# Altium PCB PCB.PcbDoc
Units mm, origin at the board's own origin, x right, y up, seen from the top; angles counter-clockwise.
Board outline 65.94 x 50 mm, 2 copper layers (Top Layer, Bottom Layer); 36 components, 28 nets, 111 pads, 85 vias.
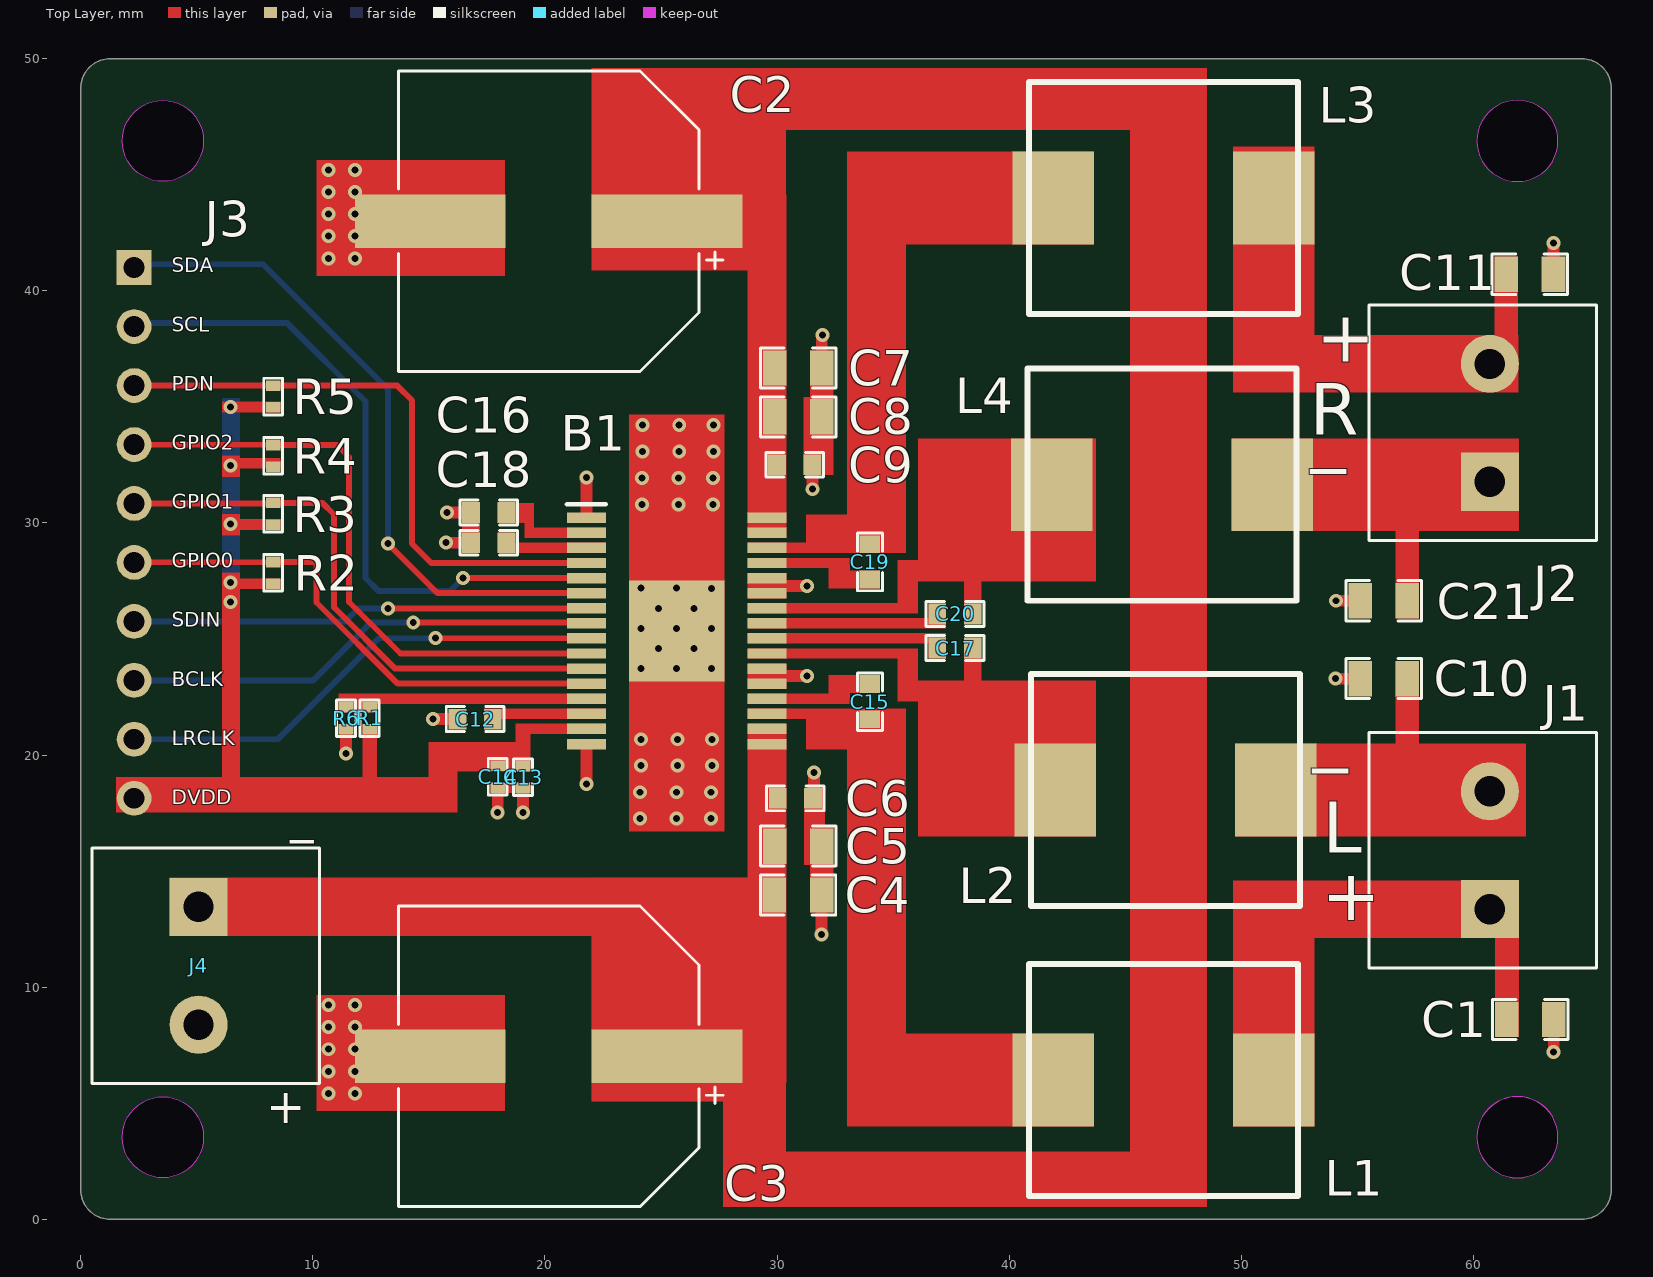
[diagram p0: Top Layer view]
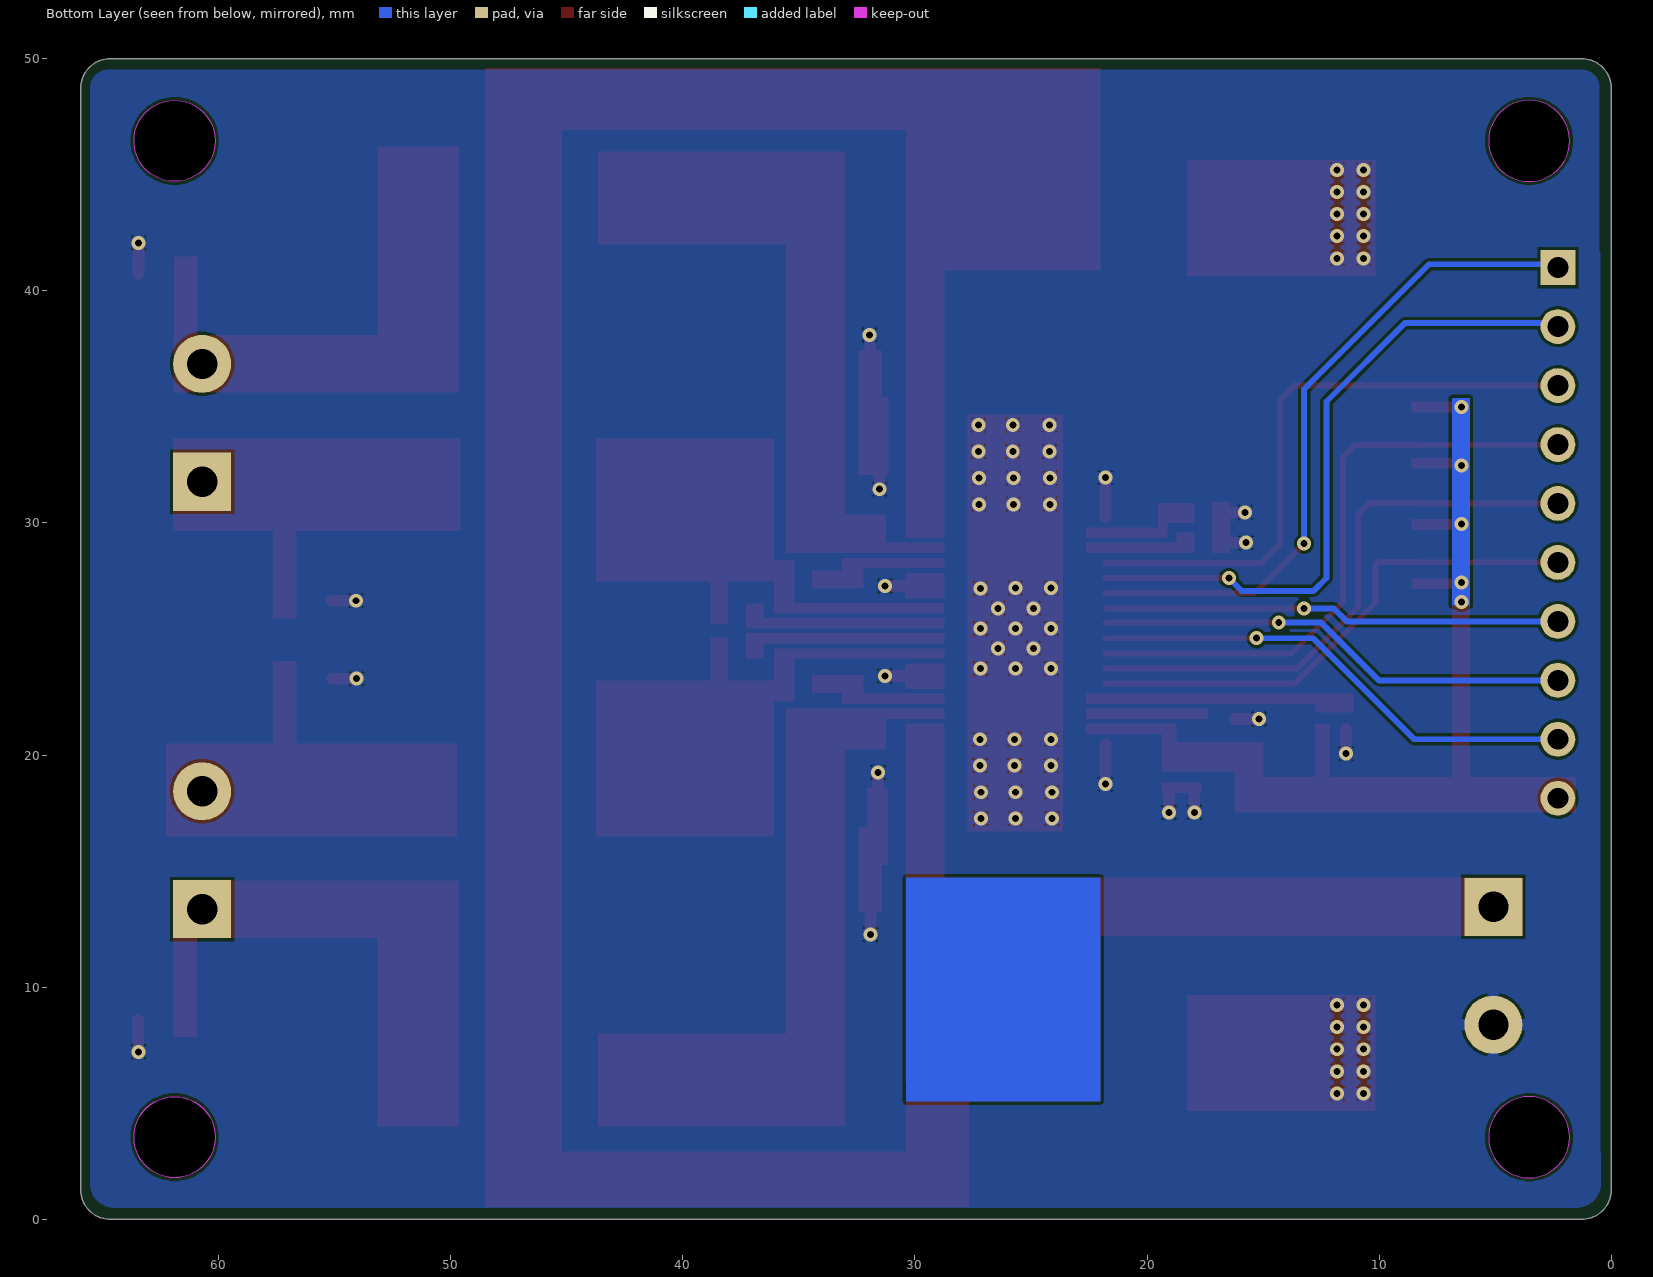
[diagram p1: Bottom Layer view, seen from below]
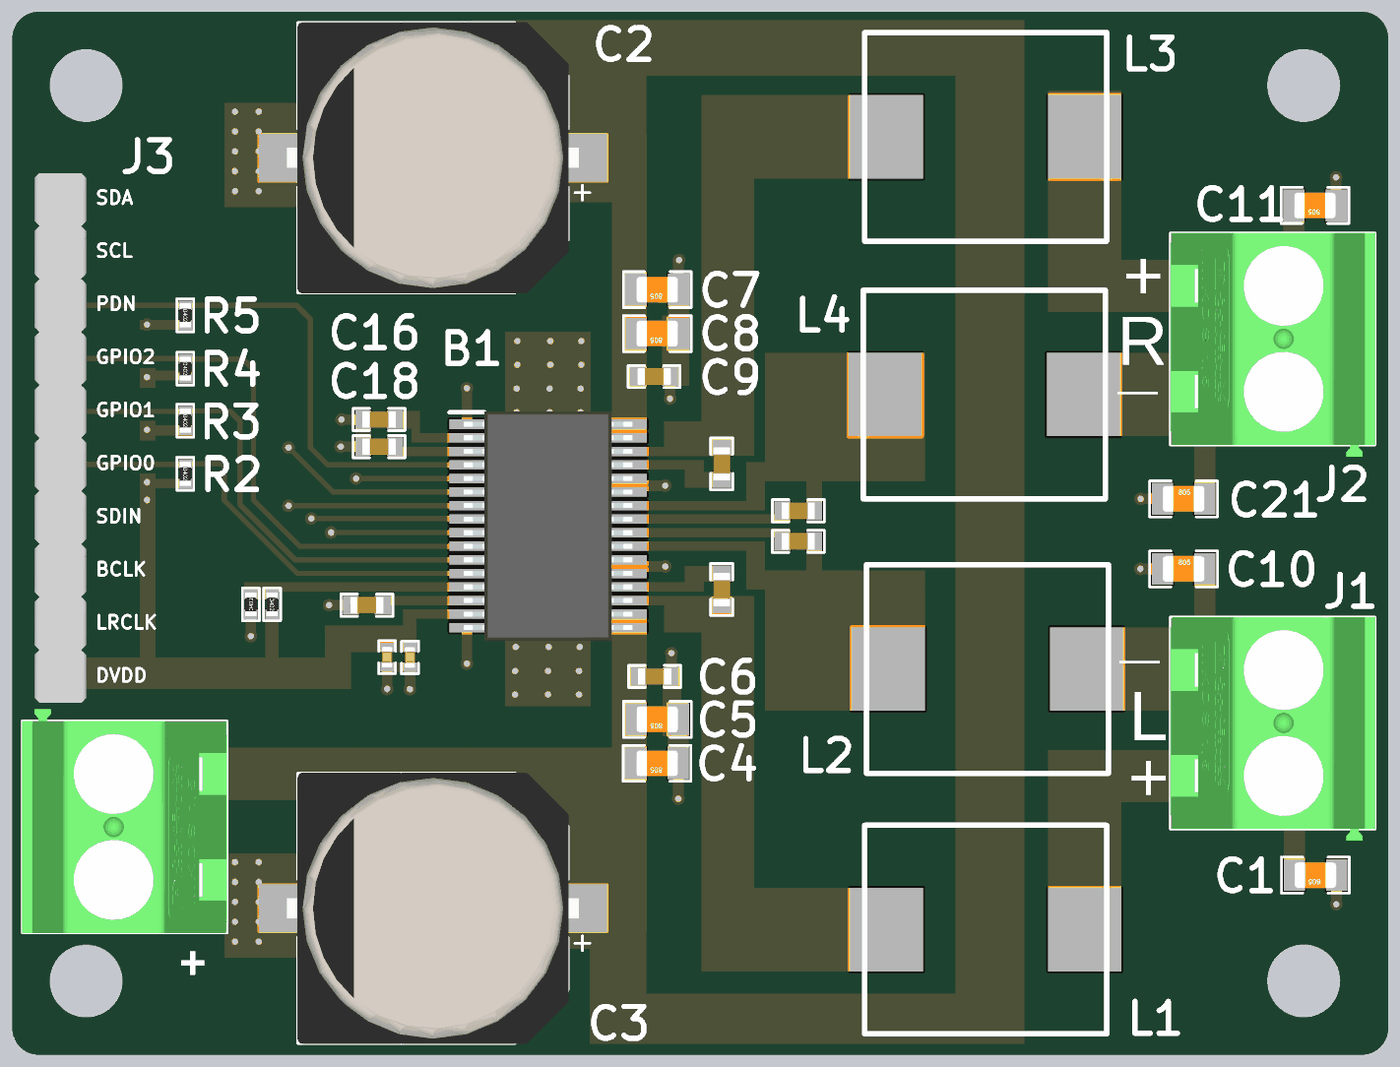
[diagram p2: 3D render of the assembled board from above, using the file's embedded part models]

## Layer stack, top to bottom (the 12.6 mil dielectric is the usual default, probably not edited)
Top Solder: solder mask 0.0102, Solder Resist, Dk 3.5
Top Layer: signal copper 0.0356
Dielectric 1: dielectric 0.32, FR-4, Dk 4.8
Bottom Layer: signal copper 0.0356
Bottom Solder: solder mask 0.0102, Solder Resist, Dk 3.5

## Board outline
1.27,0 cw(c1.27,1.27) 0,1.27 0,48.73 cw(c1.27,48.73) 1.27,50 64.668,50 cw(c64.668,48.73) 65.938,48.73 65.938,1.27 cw(c64.668,1.27) 64.668,0
cut-out: 60.142,3.54 ccw(c61.892,3.54) 61.892,1.79 ccw(c61.892,3.54) 63.642,3.54 ccw(c61.892,3.54) 61.892,5.29 ccw(c61.892,3.54)
cut-out: 60.142,3.536 ccw(c61.892,3.536) 61.892,1.786 ccw(c61.892,3.536) 63.642,3.536 ccw(c61.892,3.536) 61.892,5.286 ccw(c61.892,3.536)
cut-out: 60.142,46.464 ccw(c61.892,46.464) 61.892,44.714 ccw(c61.892,46.464) 63.642,46.464 ccw(c61.892,46.464) 61.892,48.214 ccw(c61.892,46.464)
cut-out: 3.536,44.714 cw(c3.536,46.464) 1.786,46.464 cw(c3.536,46.464) 3.536,48.214 cw(c3.536,46.464) 5.286,46.464 cw(c3.536,46.464)
cut-out: 3.536,1.786 cw(c3.536,3.536) 1.786,3.536 cw(c3.536,3.536) 3.536,5.286 cw(c3.536,3.536) 5.286,3.536 cw(c3.536,3.536)

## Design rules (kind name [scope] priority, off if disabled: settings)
Clearance [All] p1: gap=0.127 ignorepadtopadclearanceinfootprint=FALSE
HoleToHoleClearance [All] p1: gap=0.127 allowstackedmicrovias=TRUE
MinimumSolderMaskSliver [All] p1: minsoldermaskwidth=0
PolygonConnect [All] p1: connectstyle=Relief reliefconductorwidth=0.508 reliefentries=4 polygonreliefangle="90 Angle" airgapwidth=0.127
RoutingVias [All] p1: holewidth=0.3 width=0.6 viastyle="Through Hole" minholewidth=0.3 minwidth=0.6 maxholewidth=0.3 maxwidth=0.6
SilkToSilkClearance [All] p1: silktosilkclearance=0
SilkToSolderMaskClearance [IsPad] p1: minsilkscreentomaskgap=0 clearancetoexposedcopper=TRUE
SolderMaskExpansion [All] p1: expansion=0.102 istentingtop=FALSE
UnRoutedNet [All] p1: checkbadconnections=TRUE
Width [All] p1: maxlimit=1.27 minlimit=0.025 preferedwidth=0.254
25 further rules are at their usual default settings.

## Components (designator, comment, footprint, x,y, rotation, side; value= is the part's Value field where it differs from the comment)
B1 "TAS5828MDADR" SOP65P810X115-33M 25.673,25.351 r0 top
C1 "680nF" Cap-0805 62.454,8.611 r180 top
C2 "470uF" RVT470UF50V34RV0133 20.158,43 r180 top
C3 "470uF" RVT470UF50V34RV0133 20.158,7.021 r180 top
C4 "10uF" Cap-0805 30.902,13.97 r180 top
C5 "10uF" Cap-0805 30.912,16.078 r180 top
C6 "100nF" Cap-0603 30.785,18.136 r180 top
C7 "10uF" Cap-0805 30.907,36.678 r180 top
C8 "10uF" Cap-0805 30.907,34.569 r180 top
C9 "100nF" Cap-0603 30.759,32.512 r180 top
C10 "680nF" Cap-0805 56.134,23.292 r0 top
C11 "680nF" Cap-0805 62.433,40.716 r180 top
C12 "1uF" Cap-0603 16.992,21.551 r0 top
C13 "0.1uF" Cap-0402 19.054,19.05 r90 top value=100nF
C14 "0.1uF" Cap-0402 17.962,19.062 r90 top value=100nF
C15 "0.47uF" Cap-0603 34,22.3 r270 top
C16 "1uF" Cap-0603 17.577,30.451 r0 top
C17 "0.47uF" Cap-0603 37.668,24.613 r0 top
C18 "1uF" Cap-0603 17.577,29.151 r0 top
C19 "0.47uF" Cap-0603 34,28.325 r90 top
C20 "0.47uF" Cap-0603 37.668,26.079 r0 top
C21 "680nF" Cap-0805 56.134,26.648 r0 top
J1 "1715721" 1715721 60.706,15.9 r90 top
J2 "1715721" 1715721 60.706,34.315 r90 top
J3 "PZ254-1-10-Z-8.5" PZ254-1-10-Z-8.5 2.3,41 r270 top
J4 "1715721" 1715721 5.08,10.922 r270 top
L1 "10uH" BMRF00101040100MA1 41.899,6 r0 top
L2 "10uH" BMRF00101040100MA1 41.986,18.491 r0 top
L3 "10uH" BMRF00101040100MA1 41.899,44 r0 top
L4 "10uH" BMRF00101040100MA1 41.833,31.648 r0 top
R1 "0R" Res-0402 12.446,21.59 r270 top
R2 "10K" Res-0402 8.29,27.85 r270 top
R3 "10K" Res-0402 8.29,30.395 r270 top
R4 "10K" Res-0402 8.29,32.89 r270 top
R5 "10K" Res-0402 8.29,35.448 r270 top
R6 "0R" Res-0402 11.43,21.59 r90 top

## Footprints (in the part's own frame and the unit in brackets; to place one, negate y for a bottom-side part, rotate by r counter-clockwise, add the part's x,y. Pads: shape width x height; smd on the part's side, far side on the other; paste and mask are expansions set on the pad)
1715721 [mm]
  rect 2.5x2.5 / inner round 2.5 / far side rect 2.5x2.5 hole 1.3: 1(-2.54,0)
  round 2.5 hole 1.3: 2(2.54,0)
  silkscreen extent -5.08,-4.6 5.08,5.2, body extent -5.64,-4.62 5.09,5.21, height 14.2
BMRF00101040100MA1 [mm]
  rect 3.5x4 smd: 1(0,0) 2(9.5,0)
  silkscreen extent -1.05,-5 10.55,5, body extent -1.02,-4.95 10.54,4.95, height 4
Cap-0402 [mil]
  rect 18x25 smd mask+2.36: 1(-18.5,0) 2(18.5,0)
  silkscreen extent -31,-16 31,16, body extent -20,-10 20,10, height 19
Cap-0603 [mil]
  rect 30x35 smd mask+2.36: 1(-30,0) 2(30,0)
  silkscreen extent -49,-21 49,21, body extent -32,-16 31,16, height 34
Cap-0805 [mil] "SMD 0805"
  rect 40x60 smd mask+2.76: 1(-40,0) 2(40,0)
  silkscreen extent -64,-34 64,34, body extent -39,-25 39,25, height 30
PZ254-1-10-Z-8.5 [mm]
  rect 1.5x1.5 hole 0.9: 1(0,0)
  round 1.5 hole 0.9: 2(2.54,0) 3(5.08,0) 4(7.62,0) 5(10.16,0) 6(12.7,0) 7(15.24,0) 8(17.78,0) 9(20.32,0) 10(22.86,0)
  body extent -1.27,-1.25 24.13,1.25, height 9.51
Res-0402 [mil]
  rect 18x25 smd mask+2.17: 1(-18.5,0) 2(18.5,0)
  silkscreen extent -32,-17 32,16, body extent -23,-11 23,11, height 16
RVT470UF50V34RV0133 [mm]
  rect 6.5x2.3 smd paste+0 mask+0.051: 1(-5.1,0) 2(5.1,0)
  silkscreen extent -7.52,-6.48 6.48,6.48, body extent -7,-6.5 7,6.5, height 13.5
SOP65P810X115-33M [mm]
  rect 1.675x0.45 smd: 1(-3.888,4.875) 2(-3.888,4.225) 3(-3.888,3.575) 4(-3.888,2.925) 5(-3.888,2.275) 6(-3.888,1.625) 7(-3.888,0.975) 8(-3.888,0.325) 9(-3.888,-0.325) 10(-3.888,-0.975) 11(-3.888,-1.625) 12(-3.888,-2.275) 13(-3.888,-2.925) 14(-3.888,-3.575) 15(-3.888,-4.225) 16(-3.888,-4.875) 17(3.888,-4.875) 18(3.888,-4.225) 19(3.888,-3.575) 20(3.888,-2.925) 21(3.888,-2.275) 22(3.888,-1.625) 23(3.888,-0.975) 24(3.888,-0.325) 25(3.888,0.325) 26(3.888,0.975) 27(3.888,1.625) 28(3.888,2.275) 29(3.888,2.925) 30(3.888,3.575) 31(3.888,4.225) 32(3.888,4.875)
  rect 4.11x4.36 smd: 33(0,0)
  silkscreen extent -4.72,5.45 -3.05,5.45, body extent -4.05,-5.5 4.05,5.5, height 1.15

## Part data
B1: "Audio Amplifiers 50-W stereo, digital input, high-performance, closed-loop, Class-D, with integrated audio processor 32-HTSSOP -40 to 85", LCSC Part Number=C5214953, Manufacturer_Name="Texas Instruments", Mouser Part Number=595-TAS5828MDADR
C1 C10 C11 C21: library part CC0805KKX7R9BB684, "50V 680nF X7R ±10% 0805 Multilayer Ceramic Capacitors MLCC - SMD/SMT ROHS", LCSC Part Number=C107133, Manufacturer=YAGEO, Package=0805
C2 C3: library part RVT470UF50V34RV0133, "470uF 50V 50mA@120Hz ±20% SMD,D12.5xL13.5mm Aluminum Electrolytic Capacitors - SMD ROHS", LCSC Part Number=C2837182, Manufacturer=KNSCHA
C4 C5 C7 C8: library part CC0805KKX5R8BB106, "CAP CER 10UF 25V X5R 0805", Case Code (Imperial)=0805, Case Code (Metric)=2012, Dielectric=X5R, LCSC Part Number=C89831, Manufacturer=Yageo, Max Operating Temperature=85°C, Min Operating Temperature=-55°C, Resistor Type=Ceramic, Supplier Part Number 1=311-1869-1-ND, Tolerance=10%, Voltage Rating=25V
C6 C9: library part CC0603KRX5R9BB104, "CAP CER 0.1UF 50V X5R 0603", Case Code (Imperial)=0603, Case Code (Metric)=1608, Dielectric=X5R, LCSC Part Number=C110022, Manufacturer=Yageo, Max Operating Temperature=85°C, Min Operating Temperature=-55°C, Package Quantity=4000, Supplier Part Number 1=311-4046-1-ND, Tolerance=10%, Voltage Rating=50V
C12 C16 C18: library part CC0603KRX5R8BB105, "CAP CER 1UF 25V X5R 0603", Case Code (Imperial)=0603, Case Code (Metric)=1608, Dielectric=X5R, LCSC Part Number=C14664, Manufacturer=Yageo, Max Operating Temperature=85°C, Min Operating Temperature=-55°C, Package Quantity=1, Supplier Part Number 1=311-1445-1-ND, Tolerance=10%, Voltage Rating=25V
C13 C14: library part CC0402JRX7R7BB104, "CAP CER 0.1UF 16V X7R 0402", Case Code (Imperial)=0402, Case Code (Metric)=1005, Dielectric=X7R, LCSC Part Number=C541464, Manufacturer=Yageo, Max Operating Temperature=125°C, Min Operating Temperature=-55°C, Package Quantity=10000, Supplier Part Number=311-1676-1-ND, Tolerance=5%, Voltage Rating=16V
C15 C17 C19 C20: library part CC0603KRX5R9BB474, "CAP CER 0.47UF 50V X5R 0603", Capacitance=470nF, Case/Package=0603, Dielectric=X5R, LCSC Part Number=C513651, Manufacturer=Yageo, Max Operating Temperature=85°C, Min Operating Temperature=-55°C, Supplier Part Number 1=311-4047-1-ND, Tolerance=10%, Voltage Rating=50V
J1 J2 J4: "TERM BLK 2P SIDE ENT 5.08MM PCB", LCSC Part Number=C480516, Manufacturer="Phoenix Contact", Supplier Part Number=277-1263-ND
J3: "3A Direct Insert Policy 2.5mm 260℃@10S 10P 6mm -40℃~+105℃ 3mm 2.54mm Single Row Black Brass 1x10P Plugin,P=2.54mm Pin Headers ROHS", LCSC Part Number=C2894933, Manufacturer=HCTL, Package=Plugin,P{}2.54mmPlugin,P{}2.54mm
L1 L2 L3 L4: library part BMRF00101040100MA1, "6.5A 10uH Shielded inductor ±20% 7A Power Inductors ROHS", LCSC Part Number=C2903677, Manufacturer="Chilisin Elec", Package=-
R1 R6: library part RC0402FR-070RL, "RES 0 OHM JUMPER 1/16W 0402", Case Code (Imperial)=0402, Case Code (Metric)=1005, LCSC Part Number=C106231, Manufacturer=Yageo, Max Operating Temperature=155°C, Max Power Dissipation=63mW, Min Operating Temperature=-55°C, Power Rating=62.5mW, Resistor Type="Thick Film", Supplier Part Number 1=603-RC0402FR-070RL, Temperature Coefficient=200ppm/°C, Tolerance=1%, Voltage Rating=50V
R2 R3 R4 R5: library part RC0402FR-0710KL, "RES 10K OHM 1% 1/16W 0402", Case Code (Imperial)=0402, Case Code (Metric)=1005, LCSC Part Number=C60490, Manufacturer=Yageo, Max Operating Temperature=155°C, Max Power Dissipation=63mW, Min Operating Temperature=-55°C, Power Rating=62.5mW, Resistance=10kR, Resistance Tolerance=1%, Resistor Type="Thick Film", Supplier Part Number 1=603-RC0402FR-0710KL, Temperature Coefficient=100ppm/°C, Voltage Rating=50V

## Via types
v1: diameter 0.6, hole 0.3, Top Layer to Bottom Layer, 85 vias

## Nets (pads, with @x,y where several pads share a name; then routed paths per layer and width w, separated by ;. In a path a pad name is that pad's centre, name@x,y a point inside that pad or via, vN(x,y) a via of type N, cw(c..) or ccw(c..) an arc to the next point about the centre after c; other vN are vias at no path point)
ADR: B1.13 R1.1 R6.2
BCLK: B1.8 J3.8 | length 20.5
  Top Layer w0.254: v1(14.326,25.705) 21.756,25.705 B1.8
  Bottom Layer w0.254: J3.8 10.012,23.22 12.497,25.705 v1(14.326,25.705)
BST_A+: B1.20 C15.1
BST_A-: B1.24 C17.1
BST_B+: B1.29 C19.1
BST_B-: B1.25 C20.1
DVDD: B1.15 C13.2 C14.2 J3.10 R1.2 R2.2 R3.2 R4.2 R5.2 | length 0
  other v1: 6.452,26.594 6.452,27.444 6.452,29.964 6.452,32.484 6.452,35.005
GND: B1.1 B1.16 B1.21 B1.22 B1.27 B1.28 B1.33 C1.1 C2.2 C3.2 C4.1 C5.1 C6.1 C7.1 C8.1 C9.1 C10.1 C11.1 C12.1 C13.1 C14.1 C16.1 C18.1 C21.1 J4.2 R6.1 | length 23.1
  Top Layer w0.508: v1(11.43,20.062) R6.1@11.43,21.104 ; v1(15.173,21.551) C12.1@16.214,21.551 ; v1(15.735,29.151) C18.1@16.777,29.151 ; v1(15.773,30.451) C16.1 ; v1(17.962,17.535) C14.1@17.962,18.576 ; v1(19.054,17.522) C13.1@19.054,18.564 ; v1(21.785,18.749) B1.16@21.785,20.447 ; B1.1@21.785,30.255 v1(21.785,31.953) ; 29.591,27.281 v1(31.29,27.281) ; 29.596,23.407 v1(31.294,23.407) ; v1(31.522,31.454) C9.1@31.522,32.496 ; C6.1@31.585,18.136 v1(31.585,19.25) ; v1(31.918,12.272) C4.1 ; C7.1@31.923,36.694 31.923,38.045 31.953,38.075 v1(31.953,38.1) ; v1(54.06,23.292) C10.1@55.102,23.292 ; v1(54.077,26.648) C21.1 ; C11.1@63.443,40.743 63.446,40.746 63.446,42.059 v1(63.443,42.062) ; v1(63.453,7.214) 63.462,7.222 63.462,8.586 C1.1@63.47,8.594
  other v1: 10.668,5.423 11.808,5.423 10.668,6.375 11.808,6.375 10.668,7.328 11.808,7.328 10.668,8.28 11.808,8.28 10.668,9.233 11.808,9.233 24.095,17.268 25.673,17.268 27.158,17.268 24.095,18.399 25.673,18.399 27.158,18.399 24.13,19.55 25.708,19.55 27.193,19.55 24.13,20.681 25.708,20.681 27.193,20.681 24.13,23.726 25.673,23.726 27.178,23.726 24.892,24.601 26.416,24.601 24.13,25.451 25.673,25.451 27.178,25.451 24.892,26.32 26.416,26.32 27.178,27.183 24.13,27.201 25.673,27.201 24.171,30.801 25.749,30.801 27.234,30.801 24.171,31.932 25.749,31.932 27.234,31.932 24.206,33.083 25.784,33.083 27.269,33.083 24.206,34.214 25.784,34.214 27.269,34.214 10.668,41.402 11.808,41.402 10.668,42.355 11.808,42.355 10.668,43.307 11.808,43.307 10.668,44.259 11.808,44.259 10.668,45.212 11.808,45.212
GPIO0: B1.12 J3.6 R2.1 | length 22.6
  Top Layer w0.254: J3.6 2.31,28.31 8.28,28.31 R2.1 10.033,28.32 10.046,28.332 10.16,28.218 10.16,26.577 13.661,23.076 B1.12
GPIO1: B1.11 J3.5 R3.1 | length 24.8
  Top Layer w0.254: J3.5@2.286,30.988 J3.5@2.297,30.977 ; J3.5 8.265,30.84 R3.1 10.41,30.865 10.912,30.363 10.912,26.363 13.549,23.726 B1.11
GPIO2: B1.10 J3.4 R4.1 | length 26.9
  Top Layer w0.254: J3.4 2.31,33.37 8.28,33.37 R4.1 11.039,33.36 11.557,32.842 11.557,26.594 13.775,24.376 B1.10
LRCLK: B1.9 J3.9 | length 21.3
  Top Layer w0.254: v1(15.275,25.035) 21.776,25.035 B1.9
  Bottom Layer w0.254: J3.9 8.488,20.68 12.843,25.035 v1(15.275,25.035)
NetB1_2: B1.2 C16.2
NetB1_3: B1.3 C18.2
NetB1_14: B1.14 C12.2
NetC1_2: C1.2 J1.1 L1.2
NetC10_2: C10.2 J1.2 L2.2
NetC11_2: C11.2 J2.2 L3.2
NetC21_2: C21.2 J2.1 L4.2
OUT_A+: B1.19 C15.2 L1.1
OUT_A-: B1.23 C17.2 L2.1
OUT_B+: B1.30 C19.2 L3.1
OUT_B-: B1.26 C20.2 L4.1
PDN: B1.4 J3.3 R5.1 | length 26.3
  Top Layer w0.254: J3.3 2.301,35.919 8.289,35.919 R5.1 13.638,35.918 14.275,35.281 14.275,29.108 15.107,28.276 B1.4
PVDD: B1.17 B1.18 B1.31 B1.32 C2.1 C3.1 C4.2 C5.2 C6.2 C7.2 C8.2 C9.2 J4.1
SCL: B1.5 J3.2 | length 29
  Top Layer w0.254: v1(16.476,27.626) B1.5
  Bottom Layer w0.254: J3.2@2.286,38.608 8.89,38.608 12.268,35.23 12.268,27.63 12.822,27.076 15.926,27.076 v1(16.476,27.626)
SDA: B1.6 J3.1 | length 29.3
  Top Layer w0.254: v1(13.236,29.108) 15.369,26.976 B1.6
  Bottom Layer w0.254: J3.1@2.286,41.148 7.849,41.148 13.236,35.76 v1(13.236,29.108)
SDIN: B1.7 J3.7 | length 19.7
  Top Layer w0.254: v1(13.236,26.317) 13.239,26.32 21.779,26.32 B1.7
  Bottom Layer w0.254: J3.7 11.393,25.76 11.95,26.317 v1(13.236,26.317)

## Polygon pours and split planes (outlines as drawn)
GND on Bottom Layer "GND_L02_P000" (solid, pour order 0): 1.27,49.53 64.732,49.53 cw(c64.732,48.73) 65.532,48.73 65.532,1.524 cw(c64.516,1.524) 64.516,0.508 1.473,0.508 cw(c1.473,1.524) 0.457,1.524 0.457,2.866 ccw(c0.457,2.889) 0.48,2.889 0.48,41.628 cw(c0.508,41.628) 0.508,41.656 0.508,48.768 cw(c1.27,48.768)

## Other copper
Top Layer:
  rectangle net PVDD: 22.008,40.877 30.394,47.93
  rectangle net PVDD: 22.008,46.937 48.514,49.606
  rectangle net PVDD: 45.212,0.52 48.514,49.606
  rectangle net PVDD: 27.676,0.52 48.514,2.921
  rectangle net PVDD: 27.676,0.52 30.378,7.722
  rectangle net GND: 23.618,16.703 27.728,34.671
  rectangle net DVDD: 6.096,26.938 6.858,27.871
  rectangle net DVDD: 6.096,29.458 6.858,30.392
  rectangle net DVDD: 6.096,31.979 6.858,32.912
  region net GND: 32.055,18.582 31.166,18.582 31.166,15.265 32.055,15.265
  region net GND: 32.426,16.891 31.41,16.891 31.41,13.208 32.426,13.208
  rectangle net GND: 31.14,32.067 32.431,35.433
  rectangle net GND: 31.415,33.807 32.431,37.44
  rectangle net DVDD: 6.096,34.749 8.608,35.23
  rectangle net DVDD: 6.096,32.337 8.608,32.802
  rectangle net DVDD: 6.096,29.692 8.608,30.175
  rectangle net DVDD: 6.096,27.151 8.608,27.604
  rectangle net DVDD: 6.096,17.538 6.858,27.813
  rectangle net GND: 10.16,4.661 18.288,9.656
  rectangle net GND: 10.16,40.64 18.288,45.636
  rectangle net GND: 28.723,26.751 30.399,27.851
  rectangle net GND: 28.723,22.851 30.399,23.951
  rectangle net NetC1_2: 60.93,7.849 61.956,14.122
  rectangle net NetC11_2: 60.913,35.623 61.925,41.478
  rectangle net NetC10_2: 56.642,17.581 57.658,24.054
  rectangle net NetC21_2: 56.642,25.886 57.658,32.36
  rectangle net NetC11_2: 49.649,35.611 53.149,46.216
  rectangle net NetC11_2: 49.649,35.611 61.953,38.105
  rectangle net NetC21_2: 49.583,29.648 61.956,33.648
  rectangle net NetC21_2: 49.583,29.648 53.083,33.648
  rectangle net NetC1_2: 49.649,12.11 61.953,14.605
  rectangle net NetC1_2: 49.649,4 53.149,14.605
  rectangle net NetC10_2: 49.736,16.491 62.255,20.491
  rectangle net OUT_B-: 36.068,27.486 43.736,33.648
  rectangle net OUT_B-: 35.179,26.101 36.068,28.402
  rectangle net OUT_B-: 35.179,27.486 43.736,28.402
  rectangle net OUT_B-: 38.049,25.645 38.811,28.402
  rectangle net OUT_A-: 38.049,22.3 38.811,25.057
  rectangle net OUT_A-: 36.068,16.491 43.736,23.216
  rectangle net OUT_A-: 35.179,22.3 43.736,23.216
  rectangle net OUT_A-: 35.179,22.3 36.068,24.601
  rectangle net OUT_B+: 33.02,42 43.649,46
  rectangle net OUT_B+: 33.02,29.339 35.56,45.999
  rectangle net OUT_B+: 31.242,28.706 35.56,30.374
  rectangle net OUT_B+: 31.242,29.339 34.302,30.374
  rectangle net BST_B-: 36.525,25.451 37.287,26.523
  rectangle net BST_A-: 36.525,24.168 37.287,25.251
  rectangle net BST_B-: 35.179,25.451 37.287,25.901
  rectangle net BST_A-: 35.179,24.801 37.287,25.251
  rectangle net BST_A-: 28.723,24.801 35.56,25.251
  rectangle net BST_B-: 28.723,25.451 35.56,25.901
  rectangle net OUT_B-: 28.723,26.101 35.56,26.551
  rectangle net OUT_A-: 28.723,24.151 35.56,24.601
  rectangle net BST_A-: 28.723,24.801 30.399,25.251
  rectangle net BST_B-: 28.723,25.451 30.399,25.901
  rectangle net OUT_B-: 28.723,26.101 30.399,26.551
  rectangle net OUT_A-: 28.723,24.151 30.399,24.601
  rectangle net BST_B+: 28.724,28.051 33.146,28.501
  rectangle net BST_B+: 32.219,27.183 34.445,27.945
  rectangle net BST_B+: 32.219,27.183 33.146,28.424
  rectangle net OUT_B+: 33.556,28.77 34.445,29.532
  rectangle net OUT_B+: 28.723,28.701 34.445,29.151
  rectangle net BST_A+: 32.219,22.201 33.146,23.442
  rectangle net BST_A+: 32.219,22.68 34.445,23.442
  rectangle net BST_A+: 28.723,22.201 33.146,22.651
  rectangle net OUT_A+: 31.242,20.251 34.302,21.287
  rectangle net OUT_A+: 31.242,20.251 35.56,22.001
  rectangle net OUT_A+: 33.02,4 35.56,21.287
  rectangle net OUT_A+: 33.02,4 43.649,8
  rectangle net OUT_A+: 33.413,20.525 34.302,21.287
  rectangle net OUT_A+: 28.723,21.551 32.029,22.001
  rectangle net DVDD: 12.128,18.364 12.763,21.349
  rectangle net ADR: 11.111,21.831 12.763,22.651
  rectangle net ADR: 11.111,22.201 22.622,22.651
  rectangle net DVDD: 14.986,17.526 16.23,20.574
  rectangle net DVDD: 14.986,19.291 19.372,20.574
  rectangle net DVDD: 1.524,17.526 16.23,19.05
  rectangle net DVDD: 18.737,19.291 19.372,21.351
  rectangle net DVDD: 17.644,19.291 19.372,19.761
  rectangle net PVDD: 3.83,12.212 30.394,14.732
  rectangle net PVDD: 28.724,35.426 30.399,44.15
  rectangle net PVDD: 22.008,40.877 30.394,44.941
  rectangle net PVDD: 22.008,5.08 30.394,12.7
  rectangle net PVDD: 28.723,5.871 30.399,14.595
  rectangle net PVDD: 22.008,5.871 30.399,8.171
  rectangle net PVDD: 28.723,29.351 30.399,37.44
  rectangle net PVDD: 28.723,13.208 30.399,21.351
  rectangle net NetB1_14: 17.373,21.551 22.622,22.001
  rectangle net DVDD: 18.77,20.901 22.622,21.351
  region net GND: 19.372,18.364 19.372,18.808 17.644,18.808 17.644,18.364
  rectangle net GND: 16.434,28.707 17.196,30.896
  rectangle net NetB1_2: 19.126,29.351 19.533,30.861
  rectangle net NetB1_2: 17.958,30.007 19.533,30.861
  rectangle net NetB1_2: 19.126,29.351 22.622,29.801
  rectangle net NetB1_3: 17.958,28.707 18.72,29.596
  rectangle net NetB1_3: 17.958,28.701 22.622,29.151
Bottom Layer:
  rectangle net DVDD: 6.096,26.438 6.858,35.39
  rectangle net PVDD: 22.008,5.08 30.394,14.732

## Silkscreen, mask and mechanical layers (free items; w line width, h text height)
Top Overlay:
  text "SDA" at 3.917,40.792 h0.64
  text "SCL" at 3.917,38.247 h0.64
  text "+" at 53.222,36.207 h3.81
  text "PDN" at 3.917,35.702 h0.64
  text "GPIO2" at 3.917,33.156 h0.64
  text "R" at 52.954,33.071 h3.81
  text "_" at 53.002,32.068 h3.81
  text "GPIO1" at 3.917,30.611 h0.64
  text "GPIO0" at 3.917,28.066 h0.64
  text "SDIN" at 3.917,25.521 h0.64
  text "BCLK" at 3.917,22.975 h0.64
  text "LRCLK" at 3.917,20.43 h0.64
  text "_" at 53.087,19.165 h3.81
  text "DVDD" at 3.917,17.885 h0.64
  text "_" at 10.028,16.162 h2.54
  text "L" at 53.517,15.088 h3.81
  text "+" at 53.476,12.153 h3.81
  text "+" at 7.991,3.651 h2.54
Fabrication:
  drawing of 363 lines, arcs and shapes, not listed
  text "Layer" at 76.8,103 h1.5
  text "Name" at 87.063,103 h1.5
  text "Material" at 110.334,103 h1.5
  text "Thickness" at 131.853,103 h1.5
  text "Constant" at 148.12,103 h1.5
  text "Board Layer Stack" at 162.385,103 h1.5
  text "Top Overlay" at 87.063,99.998 h1.5
  text "Top Solder" at 87.063,96.996 h1.5
  text "Solder Resist" at 110.334,96.996 h1.5
  text "0.40mil" at 131.853,96.996 h1.5
  text "3.5" at 148.12,96.996 h1.5
  text "1" at 76.8,93.993 h1.5
  text "Top Layer" at 87.063,93.993 h1.5
  text "1.40mil" at 131.853,93.993 h1.5
  text "Dielectric 1" at 87.063,90.991 h1.5
  text "FR-4" at 110.334,90.991 h1.5
  text "12.60mil" at 131.853,90.991 h1.5
  text "4.8" at 148.12,90.991 h1.5
  text "2" at 76.8,87.988 h1.5
  text "Bottom Layer" at 87.063,87.988 h1.5
  text "1.40mil" at 131.853,87.988 h1.5
  text "Bottom Solder" at 87.063,84.986 h1.5
  text "Solder Resist" at 110.334,84.986 h1.5
  text "0.40mil" at 131.853,84.986 h1.5
  text "3.5" at 148.12,84.986 h1.5
  text "Bottom Overlay" at 87.063,81.983 h1.5
Drill Drawing:
  circle w0.254: c-22.844,118.842 r0.847
  lines w0.254: -23.691,115.879 -21.997,115.879 -22.844,114.186 -23.691,115.879 ; -23.691,121.806 -21.997,121.806 -21.997,123.499 -23.691,123.499 -23.691,121.806
  lines w0.381: -25.209,113.043 242.026,113.043 ; -25.209,124.473 242.026,124.473 ; -11.217,109.233 -11.217,128.283 ; 3.511,109.233 3.511,128.283 ; 31.443,109.233 31.443,128.283 ; 44.292,109.233 44.292,128.283 ; 62.931,109.233 62.931,128.283 ; 101.019,109.233 101.019,128.283 ; 116.001,109.233 116.001,128.283 ; 134.945,109.233 134.945,128.283 ; 151.45,109.233 151.45,128.283 ; 173.136,109.233 173.136,128.283 ; 207.009,109.233 207.009,128.283 ; -25.209,109.233 242.026,109.233 242.026,128.283 -25.209,128.283 -25.209,109.233
  text "Symbol" at -22.924,125.616 h1.83
  text "Count" at -10.074,125.616 h1.83
  text "Hole Size" at 4.654,125.616 h1.83
  text "Plated" at 32.586,125.616 h1.83
  text "Hole Type" at 45.435,125.616 h1.83
  text "Drill Layer Pair" at 64.074,125.616 h1.83
  text "Via/Pad" at 102.162,125.616 h1.83
  text "Pad Shape" at 117.144,125.616 h1.83
  text "Template" at 136.088,125.616 h1.83
  text "Description" at 152.593,125.616 h1.83
  text "Hole Tolerance (+)" at 174.279,125.616 h1.83
  text "Hole Tolerance (-)" at 208.152,125.616 h1.83
  text "6" at -10.074,121.806 h1.52
  text "51.18mil (1.300mm)" at 4.654,121.806 h1.52
  text "PTH" at 32.586,121.806 h1.52
  text "Round" at 45.435,121.806 h1.52
  text "Top Layer - Bottom Layer" at 64.074,121.806 h1.52
  text "Pad" at 102.162,121.806 h1.52
  text "Rounded" at 117.144,121.806 h1.52
  text "(Mixed)" at 136.088,121.806 h1.52
  text "10" at -10.074,117.996 h1.52
  text "35.43mil (0.900mm)" at 4.654,117.996 h1.52
  text "PTH" at 32.586,117.996 h1.52
  text "Round" at 45.435,117.996 h1.52
  text "Top Layer - Bottom Layer" at 64.074,117.996 h1.52
  text "Pad" at 102.162,117.996 h1.52
  text "(Mixed)" at 117.144,117.996 h1.52
  text "(Mixed)" at 136.088,117.996 h1.52
  text "85" at -10.074,114.186 h1.52
  text "11.81mil (0.300mm)" at 4.654,114.186 h1.52
  text "PTH" at 32.586,114.186 h1.52
  text "Round" at 45.435,114.186 h1.52
  text "Top Layer - Bottom Layer" at 64.074,114.186 h1.52
  text "Via" at 102.162,114.186 h1.52
  text "Rounded" at 117.144,114.186 h1.52
  text "v60h30m60" at 136.088,114.186 h1.52
  text "101 Total" at -10.074,110.376 h1.52
Board Outline:
  circle w0.254: c61.922,46.483 r1.75
  circle w0.254: c3.536,46.464 r1.75
  circle w0.254: c61.892,3.536 r1.75
  circle w0.254: c3.536,3.536 r1.75
  lines w0.254: 21.858,0 23.114,0 ; 0,1.27 ccw(c1.27,1.27) 1.27,0 64.668,0 ccw(c64.668,1.27) 65.938,1.27 65.938,48.73 ccw(c64.668,48.73) 64.668,50 59.14,50 1.27,50 ccw(c1.27,48.73) 0,48.73 0,1.27

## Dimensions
64.668,0 to 64.668,50 on Dimension
0,1.27 to 65.938,1.27 on Dimension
